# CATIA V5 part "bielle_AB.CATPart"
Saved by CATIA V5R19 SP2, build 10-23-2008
Part number: bielle_AB
Publications: "L_AB"
Bounding box of the stored display mesh (mm): x -110 to 110, y -10 to 10, z 0 to 10
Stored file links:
  F:\iaoifma\bielle_AB.CATPart
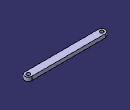
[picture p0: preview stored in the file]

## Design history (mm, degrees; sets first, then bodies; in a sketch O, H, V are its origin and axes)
Parameters
  L_AB = 200 mm
Body1 (main body)
  Sketch1 on xy-plane, origin (0, 0, 0), H (1, 0, 0), V (0, 1, 0)
    construction line L1 (-100, 0) -> (100, 0)
    point P1 (-100, 0)
    point P2 (100, 0)
    line L2 (-100, 10) -> (100, 10)
    line L3 (100, -10) -> (-100, -10)
    arc A1 centre (100, 0) radius 10 from (100, 10) to (100, -10) cw
    arc A2 centre (-100, 0) radius 10 from (-100, -10) to (-100, 10) cw
    circle A3 centre (100, 0) radius 5
    circle A4 centre (-100, 0) radius 5
    distance L1 L2 = 10
    distance L2 H = 10
    radius A4 = 5
    radius A3 = 5
    distance P2 P1 = 200 {= L_AB}
    distance P2 V = 100 {= L_AB /2}
    horizontal: L1 H
    tangency: A1 L2, A2 L2, A1 L3, A2 L3
  Pad1: profile Sketch1, direction (0, 0, 1), length 10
